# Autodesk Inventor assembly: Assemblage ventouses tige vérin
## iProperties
Created: 2011-02
Part Number: Assemblage ventouses tige vérin
Document SubType Name: Assembly
Designer: eric
Author: eric
Norme de conversion: IGES 5.3
Nom du fichier: No Iges File Name specified
Préprocesseur: Autodesk Inventor 2011
Postprocesseur: Build: 342, Release: 2008 SP3 - Date: Tue 05/27/2008
Unités envoyées: MM
Incertitude: 0.01
